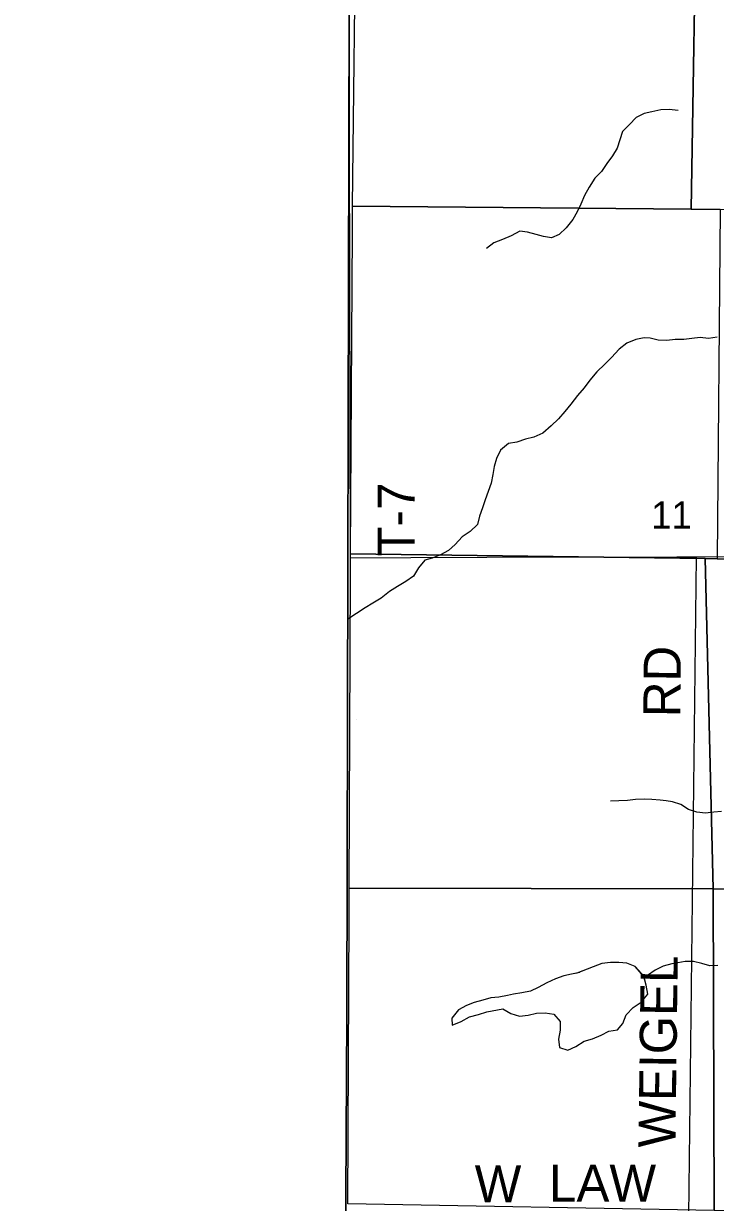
# Model space of a CAD drawing. Extents: x 1985906 to 2277390, y 930619 to 1324581.
# Drawn here: x 2110785 to 2116401, y 1174658 to 1184236 of the extents above; entities that cross this region are included whole.
import ezdxf

# ---------------------------------------------------------------- set-up
doc = ezdxf.new("R2010")
doc.units = 0
for name, color, linetype in [('GM_X_Adjacent_County', 7, 'Continuous'), ('GM_X_County', 7, 'Continuous'), ('GM_X_Minor_Lake', 7, 'Continuous'), ('GM_X_Minor_River', 7, 'Continuous'), ('GM_X_Section', 7, 'Continuous'), ('GM_X_Section_Text', 7, 'Continuous'), ('GM_X_State_Route', 7, 'Continuous'), ('GM_X_Township', 7, 'Continuous'), ('GM_X_Township_Road', 7, 'Continuous'), ('GM_X_Township_Road_Text', 7, 'Continuous')]:
    doc.layers.add(name, color=color, linetype=linetype)

msp = doc.modelspace()

# ---------------------------------------------------------------- linework, layer by layer
at = {"layer": 'GM_X_Adjacent_County'}
msp.add_lwpolyline([(2139521.7, 1198873.5), (2139549.1, 1193676.6), (2134076.1, 1193549.4), (2129443.2, 1193492.7), (2126053.1, 1193488.1), (2117908.3, 1193445.4), (2113522.7, 1193410.7), (2113466.5, 1188070.4), (2113427.5, 1184373.7), (2113417, 1179845.3), (2113408.4, 1176168.2), (2113398.8, 1174226.6), (2113371.6, 1168723.2), (2113358.2, 1166007.9), (2106159.1, 1165987.2)], dxfattribs=at)
at = {"layer": 'GM_X_County'}
msp.add_lwpolyline([(2151106.9, 1193912.6), (2145028.4, 1193800.8), (2144321.2, 1193786.8), (2140581.8, 1193696.4), (2139549.1, 1193676.6), (2134076.1, 1193549.4), (2129443.2, 1193492.7), (2126053.1, 1193488.1), (2117908.3, 1193445.4), (2113522.7, 1193410.7), (2113466.5, 1188070.4), (2113427.5, 1184373.7), (2113417, 1179845.3), (2113408.4, 1176168.2), (2113398.8, 1174226.6), (2113371.6, 1168723.2)], dxfattribs=at)
at = {"layer": 'GM_X_Minor_Lake'}
for points in [[(2115820.7, 1176495.1), (2115748.8, 1176574.9), (2115680.4, 1176600.8), (2115616.2, 1176608.6), (2115550, 1176608.4), (2115479.8, 1176600.1), (2115407.7, 1176571.8), (2115275.8, 1176521.9)], [(2115826.6, 1176488.6), (2115748.8, 1176574.9), (2115680.4, 1176600.8), (2115616.2, 1176608.6), (2115550, 1176608.4), (2115479.8, 1176600.1), (2115407.7, 1176571.8), (2115297.4, 1176530)], [(2115301.5, 1176527.2), (2115233.3, 1176513), (2115171.2, 1176498.7), (2115103.1, 1176474.4), (2115031, 1176442), (2114963, 1176403.6), (2114898.9, 1176375.2), (2114828.7, 1176361), (2114762.5, 1176350.7), (2114712.4, 1176338.5), (2114642.2, 1176326.2), (2114578.1, 1176319.9), (2114513.9, 1176301.7), (2114443.8, 1176283.3), (2114379.7, 1176257), (2114315.6, 1176222.7), (2114261.8, 1176156.2), (2114264, 1176098), (2114336.1, 1176128.3), (2114404.2, 1176166.7), (2114478.3, 1176185.1), (2114546.5, 1176205.4), (2114674.8, 1176229.9), (2114739.2, 1176191.9), (2114809.5, 1176172.1), (2114881.7, 1176180.4), (2114947.8, 1176194.7), (2115020.1, 1176198.9), (2115088.3, 1176187.1), (2115140.8, 1176129), (2115141.1, 1176056.7), (2115127.4, 1175984.4), (2115135.7, 1175916.1), (2115202, 1175894.2), (2115268.1, 1175924.6), (2115334.1, 1175969), (2115404.3, 1175987.3), (2115472.4, 1176017.7), (2115536.4, 1176050), (2115606.6, 1176060.3), (2115648.5, 1176110.7), (2115676.3, 1176183.1), (2115734.2, 1176241.5), (2115798.2, 1176285.9), (2115852.1, 1176350.3), (2115839.8, 1176422.6), (2115823.4, 1176484.8)], [(2115275.8, 1176521.9), (2115233.3, 1176513), (2115171.2, 1176498.7), (2115103.1, 1176474.4), (2115031, 1176442), (2114963, 1176403.6), (2114898.9, 1176375.2), (2114828.7, 1176361), (2114762.5, 1176350.7), (2114712.4, 1176338.5), (2114642.2, 1176326.2), (2114578.1, 1176319.9), (2114513.9, 1176301.7), (2114443.8, 1176283.3), (2114379.7, 1176257), (2114315.6, 1176222.7), (2114261.8, 1176156.2), (2114264, 1176098), (2114336.1, 1176128.3), (2114404.2, 1176166.7), (2114478.3, 1176185.1), (2114546.5, 1176205.4), (2114674.8, 1176229.9), (2114739.2, 1176191.9), (2114809.5, 1176172.1), (2114881.7, 1176180.4), (2114947.8, 1176194.7), (2115020.1, 1176198.9), (2115088.3, 1176187.1), (2115140.8, 1176129), (2115141.1, 1176056.7), (2115127.4, 1175984.4), (2115135.7, 1175916.1), (2115202, 1175894.2), (2115268.1, 1175924.6), (2115334.1, 1175969), (2115404.3, 1175987.3), (2115472.4, 1176017.7), (2115536.4, 1176050), (2115606.6, 1176060.3), (2115648.5, 1176110.7), (2115676.3, 1176183.1), (2115734.2, 1176241.5), (2115798.2, 1176285.9), (2115852.1, 1176350.3), (2115839.8, 1176422.6), (2115820.7, 1176495.1)]]:
    msp.add_lwpolyline(points, dxfattribs=at)
at = {"layer": 'GM_X_Minor_River'}
for points in [[(2116098.5, 1183529.4), (2116026.3, 1183537.2), (2115958.1, 1183535), (2115885.9, 1183518.7), (2115821.7, 1183504.4), (2115757.7, 1183472.1), (2115703.8, 1183415.6), (2115647.8, 1183359.2), (2115624.1, 1183290.8), (2115602.3, 1183224.5), (2115566.4, 1183162.1), (2115520.6, 1183097.7), (2115474.7, 1183035.3), (2115422.8, 1182978.8), (2115375, 1182906.4), (2115339.2, 1182838), (2115309.4, 1182769.6), (2115277.5, 1182705.2), (2115243.7, 1182642.8), (2115189.8, 1182576.4), (2115131.9, 1182521.9), (2115069.8, 1182495.6), (2115005.6, 1182505.5), (2114945.3, 1182523.3), (2114875, 1182541.2), (2114812.7, 1182549), (2114742.7, 1182512.6), (2114672.6, 1182482.2), (2114602.5, 1182453.9), (2114542.5, 1182409.5)], [(2116415.9, 1181688.7), (2116343.7, 1181678.4), (2116277.4, 1181686.2), (2116209.3, 1181678), (2116145.1, 1181669.7), (2116074.9, 1181669.5), (2116006.7, 1181661.2), (2115936.4, 1181665), (2115872.1, 1181680.9), (2115822, 1181682.7), (2115753.8, 1181668.4), (2115681.7, 1181638.1), (2115619.7, 1181591.6), (2115557.8, 1181523.1), (2115501.9, 1181468.7), (2115437.9, 1181406.3), (2115382.1, 1181339.8), (2115336.2, 1181275.4), (2115280.3, 1181212.9), (2115228.4, 1181144.5), (2115178.5, 1181084), (2115126.6, 1181025.6), (2115068.7, 1180967.2), (2115000.7, 1180908.7), (2114926.7, 1180876.3), (2114858.5, 1180860), (2114788.4, 1180835.7), (2114720.2, 1180823.4), (2114656.2, 1180769), (2114624.4, 1180702.6), (2114604.7, 1180638.2), (2114594.9, 1180571.9), (2114579.2, 1180501.6), (2114557.4, 1180435.2), (2114531.6, 1180366.8), (2114509.9, 1180302.5), (2114486.1, 1180234.1), (2114468.3, 1180165.8), (2114410.4, 1180109.4), (2114346.4, 1180067), (2114288.5, 1180004.5), (2114234.5, 1179956.1), (2114170.5, 1179919.8), (2114102.4, 1179891.4), (2114042.2, 1179877.1), (2113990.3, 1179814.7), (2113950.5, 1179746.3), (2113886.5, 1179703.9), (2113820.5, 1179663.5), (2113756.5, 1179621.1)], [(2113756.5, 1179621.1), (2113686.5, 1179568.6), (2113620.4, 1179526.2), (2113558.4, 1179489.9), (2113415.8, 1179396.3)], [(2113488, 1178582.7), (2113488.3, 1178581.8)], [(2116449.4, 1177834.6), (2116387.2, 1177828.4), (2116319, 1177822.1), (2116250.8, 1177827.9), (2116182.4, 1177849.8), (2116120, 1177891.7), (2116051.7, 1177913.6), (2116001.5, 1177921.5), (2115951.3, 1177925.3), (2115885.1, 1177933.1), (2115822.9, 1177934.9), (2115752.7, 1177930.7), (2115686.5, 1177922.4), (2115616.2, 1177922.2), (2115548, 1177917.9)], [(2116420.9, 1176583.2), (2116354.7, 1176581), (2116290.4, 1176598.9), (2116222.1, 1176616.7), (2116155.9, 1176616.5), (2116095.8, 1176604.2), (2116045.6, 1176598), (2115977.5, 1176577.7), (2115911.4, 1176545.4), (2115849.4, 1176503), (2115834.9, 1176496.9), (2115822.5, 1176492.7)]]:
    msp.add_lwpolyline(points, dxfattribs=at)
at = {"layer": 'GM_X_Section'}
for points in [[(2113486.5, 1185552.5), (2116249.4, 1185535.4), (2116204.6, 1182728.1), (2113455.9, 1182753.7), (2113483.7, 1185322)], [(2116249.4, 1185535.4), (2118593.2, 1185521), (2118640.2, 1182705.4), (2116439.2, 1182725.9), (2116204.6, 1182728.1)], [(2113455.9, 1182753.7), (2116204.6, 1182728.1), (2116439.2, 1182725.9), (2116416.2, 1179888.1), (2116316.6, 1179889.5), (2113437.9, 1179927.3), (2113454.6, 1182546.1)], [(2113437.9, 1179927.3), (2116316.6, 1179889.5), (2116382.1, 1177205.1), (2113428.9, 1177210.9), (2113439.5, 1179752.7)], [(2116316.6, 1179889.5), (2116416.2, 1179888.1), (2118654.3, 1179886), (2118674.3, 1179886.1), (2118708.7, 1177200.5), (2116382.1, 1177205.1)], [(2113428.9, 1177210.9), (2116382.1, 1177205.1), (2116391, 1174593), (2113415.9, 1174646.2), (2113428.2, 1176982.2)], [(2116382.1, 1177205.1), (2118708.7, 1177200.5), (2118740.5, 1174547.6), (2116391, 1174593)]]:
    msp.add_lwpolyline(points, close=True, dxfattribs=at)
at = {"layer": 'GM_X_State_Route'}
msp.add_lwpolyline([(2113437.4, 1179896.3), (2113927.5, 1179898.9), (2114545.9, 1179900.9), (2116086.6, 1179903), (2116247.9, 1179904), (2117525.9, 1179906.1), (2118650, 1179910.2), (2119351, 1179909.2), (2120453.3, 1179913.3), (2121900, 1179912.3), (2122102.3, 1179913.2)], dxfattribs=at)
at = {"layer": 'GM_X_Township'}
msp.add_lwpolyline([(2113371.6, 1168723.2), (2113398.8, 1174226.6), (2113408.4, 1176168.2), (2113417, 1179845.3), (2113427.5, 1184373.7), (2113466.5, 1188070.4), (2113522.7, 1193410.7), (2117908.3, 1193445.4), (2126053.1, 1193488.1)], dxfattribs=at)
at = {"layer": 'GM_X_Township_Road'}
for points in [[(2113437.4, 1179896.3), (2113427.5, 1184373.7), (2113466.5, 1188070.4)], [(2116186.2, 1174545.7), (2116247.9, 1179904)]]:
    msp.add_lwpolyline(points, dxfattribs=at)

# ---------------------------------------------------------------- texts
at = {"layer": 'GM_X_Section_Text'}
msp.add_text('11', height=221, rotation=0.00001, dxfattribs=at).set_placement((2115879.1, 1180132.1))
at = {"layer": 'GM_X_Township_Road_Text'}
for s, rotation, p in [('T-7', 90, (2113959.4, 1179905.2)), ('RD', 89.50633, (2116115.4, 1178599.4)), ('WEIGEL', 89.28164, (2116075.7, 1175101.9)), ('W', 0.00001, (2114446.9, 1174659.6)), ('LAW', 0.00001, (2115049.7, 1174664.1))]:
    msp.add_text(s, height=300, rotation=rotation, dxfattribs=at).set_placement(p)

doc.saveas('drawing.dxf')
